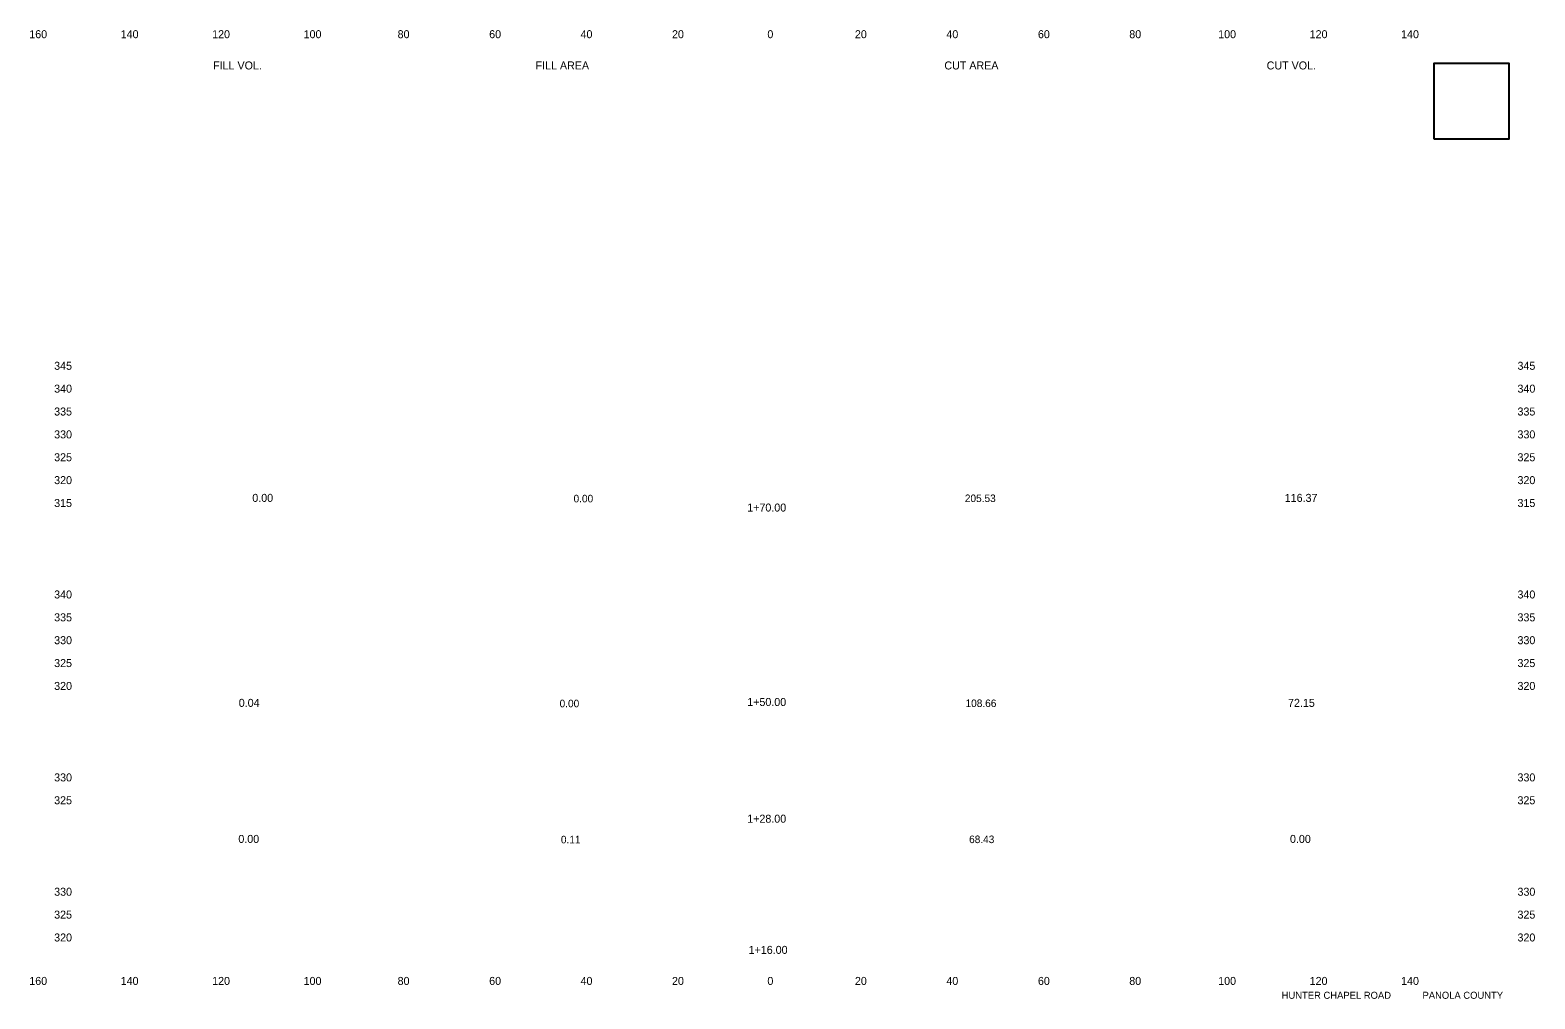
# Model space of a CAD drawing. Extents: x 21481 to 21810, y 6472 to 6914.
# Drawn here: x 21480.9 to 21809.9, y 6472.3 to 6684.1 of the extents above; entities that cross this region are included whole.
import ezdxf

# ---------------------------------------------------------------- set-up
doc = ezdxf.new("R2010")
doc.units = 0
for name, color, linetype in [('ALI_DESIGN_SECONDARY_STA', 7, 'Continuous'), ('SHEET_CONSULTANT_STAMP', 7, 'Continuous'), ('XS_SHEET_EW_TX_AREA', 7, 'Continuous'), ('XS_SHEET_EW_TX_VOLUME', 7, 'Continuous'), ('XS_SHEET_LABELS_ELEVATION', 7, 'Continuous'), ('XS_SHEET_LABELS_OFFSET', 7, 'Continuous'), ('XS_SHEET_LABELS_STATION', 7, 'Continuous'), ('XS_SHEET_TX', 7, 'Continuous')]:
    doc.layers.add(name, color=color, linetype=linetype)

msp = doc.modelspace()

# ---------------------------------------------------------------- linework, layer by layer
at = {"layer": 'SHEET_CONSULTANT_STAMP'}
msp.add_lwpolyline([(21787.84, 6660.34), (21804.34, 6660.34), (21804.34, 6676.84), (21787.84, 6676.84)], close=True, dxfattribs=at)

# ---------------------------------------------------------------- texts
at = {"layer": 'ALI_DESIGN_SECONDARY_STA'}
for s, p in [('HUNTER CHAPEL ROAD ', (21754.57, 6472.31)), ('PANOLA COUNTY', (21785.37, 6472.31))]:
    msp.add_text(s, height=1.54, dxfattribs=at).set_placement(p)
at = {"layer": 'XS_SHEET_EW_TX_AREA'}
for s, p in [('0.00', (21599.72, 6580.86)), ('205.53', (21685.29, 6580.92)), ('0.00', (21596.67, 6536.05)), ('108.66', (21685.44, 6536.1)), (' 0.11 ', (21596.34, 6506.3)), ('68.43', (21686.22, 6506.35))]:
    msp.add_text(s, height=1.65, dxfattribs=at).set_placement(p)
at = {"layer": 'XS_SHEET_EW_TX_VOLUME'}
for s, p in [('0.00', (21529.47, 6580.96)), ('116.37', (21755.24, 6580.96)), ('0.04', (21526.51, 6536.14)), ('72.15', (21755.96, 6536.14)), ('0.00', (21526.42, 6506.39)), ('0.00', (21756.39, 6506.39))]:
    msp.add_text(s, height=1.75, dxfattribs=at).set_placement(p)
at = {"layer": 'XS_SHEET_LABELS_ELEVATION'}
for s, p in [('  345  ', (21484.84, 6609.84)), ('  345  ', (21804.84, 6609.84)), ('  340  ', (21484.84, 6604.84)), ('  340  ', (21804.84, 6604.84)), ('  335  ', (21484.84, 6599.84)), ('  335  ', (21804.84, 6599.84)), ('  330  ', (21484.84, 6594.84)), ('  330  ', (21804.84, 6594.84)), ('  325  ', (21484.84, 6589.84)), ('  325  ', (21804.84, 6589.84)), ('  320  ', (21484.84, 6584.84)), ('  320  ', (21804.84, 6584.84)), ('  315  ', (21484.84, 6579.84)), ('  315  ', (21804.84, 6579.84)), ('  340  ', (21484.84, 6559.84)), ('  340  ', (21804.84, 6559.84)), ('  335  ', (21484.84, 6554.84)), ('  335  ', (21804.84, 6554.84)), ('  330  ', (21484.84, 6549.84)), ('  330  ', (21804.84, 6549.84)), ('  325  ', (21484.84, 6544.84)), ('  325  ', (21804.84, 6544.84)), ('  320  ', (21484.84, 6539.84)), ('  320  ', (21804.84, 6539.84)), ('  330  ', (21484.84, 6519.84)), ('  330  ', (21804.84, 6519.84)), ('  325  ', (21484.84, 6514.84)), ('  325  ', (21804.84, 6514.84)), ('  330  ', (21484.84, 6494.84)), ('  330  ', (21804.84, 6494.84)), ('  325  ', (21484.84, 6489.84)), ('  325  ', (21804.84, 6489.84)), ('  320  ', (21484.84, 6484.84)), ('  320  ', (21804.84, 6484.84))]:
    msp.add_text(s, height=1.75, dxfattribs=at).set_placement(p)
at = {"layer": 'XS_SHEET_LABELS_OFFSET'}
for s, p in [('  160  ', (21479.4, 6682.34)), ('  140  ', (21499.39, 6682.34)), ('  120  ', (21519.39, 6682.34)), ('  100  ', (21539.39, 6682.34)), ('  80  ', (21559.95, 6682.34)), ('  60  ', (21579.97, 6682.34)), ('  40  ', (21599.95, 6682.34)), ('  20  ', (21619.95, 6682.34)), ('  0  ', (21640.81, 6682.34)), ('  0  ', (21640.81, 6682.34)), ('  20  ', (21659.95, 6682.34)), ('  40  ', (21679.95, 6682.34)), ('  60  ', (21699.97, 6682.34)), ('  80  ', (21719.95, 6682.34)), ('  100  ', (21739.39, 6682.34)), ('  120  ', (21759.39, 6682.34)), ('  140  ', (21779.39, 6682.34)), ('  160  ', (21479.4, 6475.34)), ('  140  ', (21499.39, 6475.34)), ('  120  ', (21519.39, 6475.34)), ('  100  ', (21539.39, 6475.34)), ('  80  ', (21559.95, 6475.34)), ('  60  ', (21579.97, 6475.34)), ('  40  ', (21599.95, 6475.34)), ('  20  ', (21619.95, 6475.34)), ('  0  ', (21640.81, 6475.34)), ('  0  ', (21640.81, 6475.34)), ('  20  ', (21659.95, 6475.34)), ('  40  ', (21679.95, 6475.34)), ('  60  ', (21699.97, 6475.34)), ('  80  ', (21719.95, 6475.34)), ('  100  ', (21739.39, 6475.34)), ('  120  ', (21759.39, 6475.34)), ('  140  ', (21779.39, 6475.34))]:
    msp.add_text(s, height=1.75, dxfattribs=at).set_placement(p)
at = {"layer": 'XS_SHEET_LABELS_STATION'}
for s, p in [('  1+70.00  ', (21636.4, 6578.84)), ('  1+50.00  ', (21636.4, 6536.33)), ('  1+28.00  ', (21636.4, 6510.81)), ('  1+16.00  ', (21636.7, 6482.13))]:
    msp.add_text(s, height=1.75, dxfattribs=at).set_placement(p)
at = {"layer": 'XS_SHEET_TX'}
for s, p in [('FILL VOL.', (21520.9, 6675.51)), ('FILL AREA', (21591.41, 6675.51)), ('CUT AREA', (21680.81, 6675.51)), ('CUT VOL.', (21751.29, 6675.51))]:
    msp.add_text(s, height=1.75, dxfattribs=at).set_placement(p)

doc.saveas('drawing.dxf')
